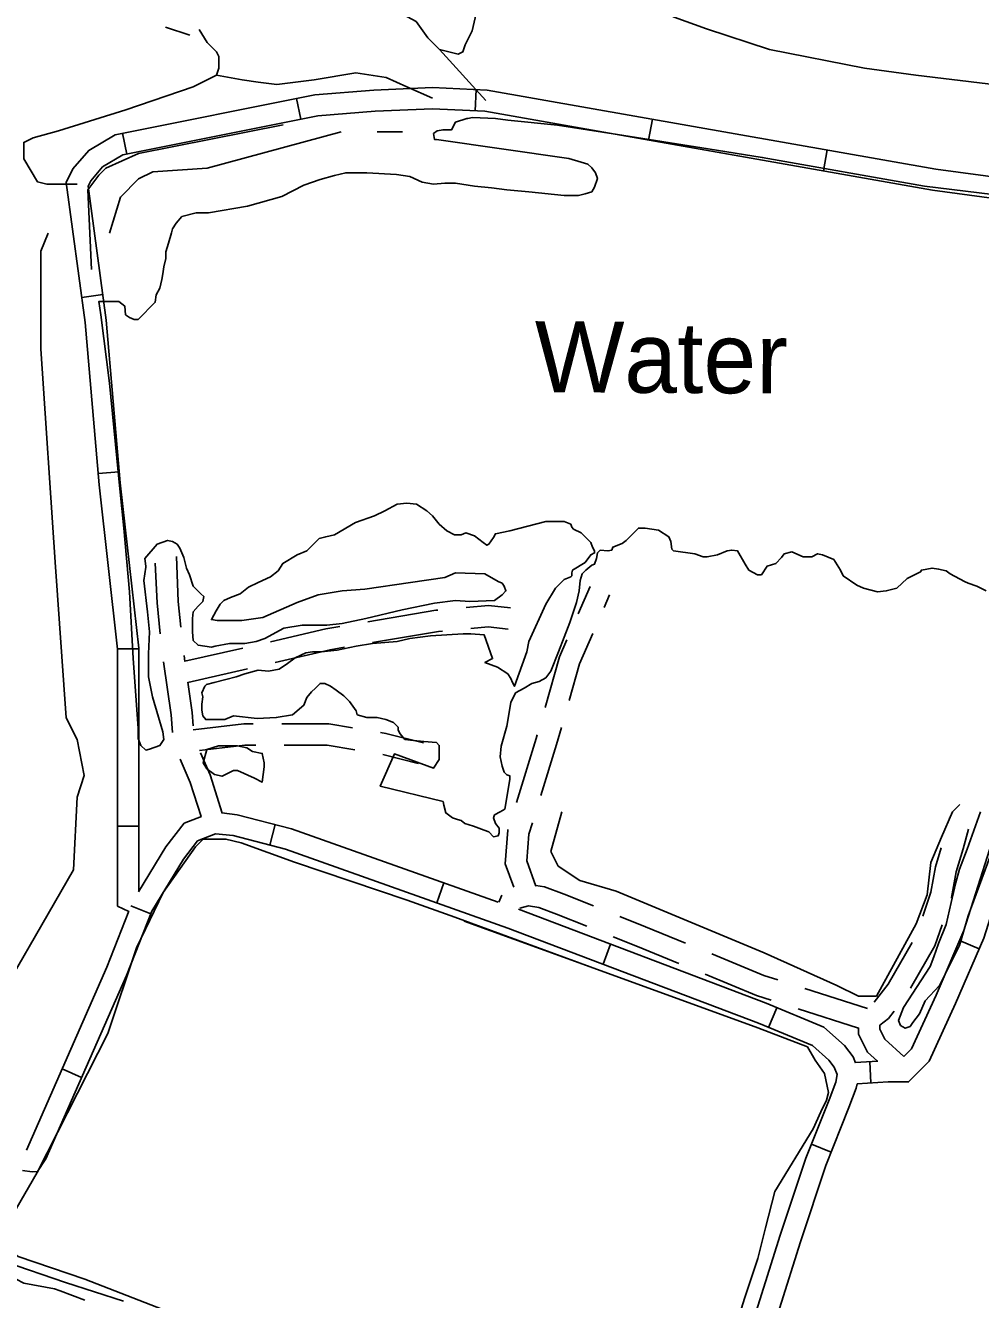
# Model space of a CAD drawing. Extents: x 3355677 to 3393573, y 612928 to 638357.
# Drawn here: x 3373580 to 3374925, y 633662 to 635458 of the extents above; entities that cross this region are included whole.
import ezdxf

# ---------------------------------------------------------------- set-up
doc = ezdxf.new("R2010")
doc.units = 0
for name, color, linetype in [('V-RIVR-IDEN', 7, 'Continuous'), ('V-ROAD-CNTR', 7, 'Continuous'), ('V-TOPO-SHOR', 7, 'Continuous')]:
    doc.layers.add(name, color=color, linetype=linetype)

msp = doc.modelspace()

# ---------------------------------------------------------------- linework, layer by layer
at = {"layer": 'V-ROAD-CNTR'}
for p, q in [((3373777.1, 635455.1), (3373811.6, 635444.1)), ((3373961.8, 635354.8), (3373967.7, 635325.4)), ((3374214.5, 635367.2), (3374213.2, 635337.3)), ((3374462.9, 635325.6), (3374457.7, 635296)), ((3373716.7, 635305.8), (3373722.5, 635276.4)), ((3374709.1, 635282.2), (3374703.9, 635252.6)), ((3373659.1, 635074.4), (3373688.8, 635078.5)), ((3373682.1, 634826.3), (3373712, 634828.8)), ((3374358.2, 634628.4), (3374375.1, 634667.2)), ((3374394.8, 634637.4), (3374402.6, 634655.3)), ((3373709.6, 634579.1), (3373739.6, 634579.1)), ((3373804.5, 634561.7), (3373886.2, 634580.1)), ((3373808.7, 634531.9), (3373892.8, 634550.8)), ((3374083.2, 634430.1), (3374133.2, 634417.6)), ((3373931.8, 634331.5), (3373924.2, 634302.4)), ((3374880.5, 634337.5), (3374881.5, 634341.2)), ((3373709.6, 634329.1), (3373739.6, 634329.1)), ((3374169.3, 634249.5), (3374159.2, 634221.2)), ((3374250.8, 634232.1), (3374246.7, 634222.3)), ((3373728.4, 634217), (3373756.4, 634206)), ((3374404.1, 634162.9), (3374393.5, 634134.9)), ((3374923.1, 634156.3), (3374895.5, 634168.2)), ((3374765.8, 634072.5), (3374677.7, 634100.6)), ((3374638.1, 634073.5), (3374626.6, 634045.8)), ((3374753.4, 634044.9), (3374668.5, 634072)), ((3374770.8, 633967.5), (3374769.1, 633997.4)), ((3373631.6, 633987.2), (3373659, 633975.2)), ((3374714.8, 633870.1), (3374687, 633881.3))]:
    msp.add_line(p, q, dxfattribs=at)
for points in [[(3373774.9, 635622.4), (3373950.4, 635547.9), (3374009.3, 635521.8), (3374094.3, 635482.5), (3374130.3, 635462.9), (3374146.7, 635440), (3374163.1, 635423.6), (3374228.5, 635351.6)], [(3374163.1, 635423.6), (3374189.2, 635417.1), (3374195.8, 635420.3), (3374199, 635430.1), (3374208.9, 635449.8), (3374221.9, 635505.4), (3374228.5, 635528.3), (3374221.9, 635551.2), (3374218.7, 635574.1), (3374212.1, 635590.5), (3374205.6, 635603.6), (3374205.6, 635617.6)], [(3374230.8, 635613.8), (3374251.4, 635603.6), (3374339.7, 635554.5), (3374418.3, 635508.7), (3374493.5, 635469.4), (3374539.3, 635453), (3374627.7, 635423.6), (3374761.8, 635397.4), (3374833.8, 635387.6), (3375075.9, 635358.2), (3375341, 635335.3), (3375422.8, 635318.9), (3375471.9, 635305.8), (3375478.4, 635299.3), (3375484.9, 635286.2), (3375481.7, 635263.3), (3375449, 635165.1), (3375344.2, 634900.1), (3375265.7, 634697.2), (3375213.4, 634556.5), (3375118.5, 634275.1), (3375102.1, 634242.4), (3375092.3, 634229.3), (3375082.7, 634224.5)], [(3373652.6, 635233.8), (3373610.1, 635233.8), (3373597, 635237.1), (3373577.4, 635269.8), (3373577.4, 635292.7), (3373590.5, 635299.3), (3373626.4, 635309.1), (3373721.3, 635338.5), (3373816.2, 635371.2), (3373848.9, 635387.6), (3373852.2, 635397.4), (3373852.2, 635413.8), (3373848.9, 635420.3), (3373835.9, 635433.4), (3373824.4, 635452)], [(3374153.2, 635354.9), (3374117.2, 635371.2), (3374087.8, 635384.3), (3374045.3, 635390.9), (3373986.4, 635381.1), (3373934, 635374.5), (3373907.8, 635377.8), (3373884.9, 635381.1), (3373848.9, 635387.6)], [(3373725.3, 634208.9), (3373709.6, 634216.8), (3373709.6, 634432.2), (3373709.6, 634578.6), (3373683.5, 634810.3), (3373663.9, 635039.1), (3373637.1, 635236.4), (3373646.6, 635255.3), (3373669, 635281.4), (3373706, 635303.6), (3373987.6, 635360), (3374070.5, 635366.6), (3374153.3, 635369.9), (3374230.1, 635366.6), (3374862.3, 635255.2), (3375103.7, 635222.6), (3375189.6, 635216), (3375207, 635211.6), (3375243.8, 635183), (3375248.1, 635148.8), (3375241.2, 635089.8), (3375165.4, 634869.1), (3375002, 634382), (3374992.3, 634346.4)], [(3373739.6, 634237.5), (3373739.6, 634432.2), (3373739.6, 634580.3), (3373713.4, 634813.2), (3373693.7, 635042.4), (3373668.1, 635231.3), (3373671.8, 635238.5), (3373688.6, 635258.2), (3373717, 635275.2), (3373991.7, 635330.2), (3374072.3, 635336.6), (3374153.2, 635339.9), (3374226.9, 635336.7), (3374857.7, 635225.5), (3375100.5, 635192.7), (3375184.8, 635186.2), (3375193.6, 635184), (3375215.6, 635166.9), (3375217.9, 635148.7), (3375211.7, 635096.5), (3375137, 634878.7), (3374973.2, 634390.7), (3374963.3, 634354.3)], [(3373798.8, 634609.6), (3373795.2, 634645.9), (3373792.4, 634709.4)], [(3373769.6, 634600.4), (3373765.3, 634643.8), (3373762.8, 634700.1)], [(3374200.7, 634637.5), (3374231.9, 634640.3), (3374262.9, 634636.9)], [(3374062.2, 634617.3), (3374157.8, 634633.6), (3374160.8, 634633.8)], [(3373925.2, 634589), (3374003, 634607.2), (3374022.8, 634610.6)], [(3374068.8, 634588), (3374161.7, 634603.8), (3374167.4, 634604.3)], [(3374207.3, 634607.9), (3374231.6, 634610.2), (3374259.6, 634607)], [(3374345.7, 634506.5), (3374360.4, 634558), (3374378.9, 634600.7)], [(3374311.7, 634496.7), (3374332.1, 634568.1), (3374342.3, 634591.7)], [(3373804.5, 634561.3), (3373803.3, 634569.9)], [(3373931.7, 634559.8), (3374009, 634577.8), (3374029.4, 634581.3)], [(3373787, 634461.5), (3373784.9, 634486.1), (3373774.3, 634560.7)], [(3373816.3, 634470.8), (3373814.8, 634489.5), (3373808.7, 634532.1)], [(3373816.3, 634465.2), (3373887.3, 634473.4), (3373900.8, 634473.4)], [(3373940.8, 634473.4), (3374007.2, 634473.4), (3374040.4, 634467.8)], [(3374079.8, 634461.3), (3374087.6, 634460), (3374140.5, 634446.7)], [(3374271.4, 634362.6), (3374299.2, 634452.8), (3374300.7, 634458.2)], [(3374305.8, 634372.4), (3374327.9, 634444.3), (3374334.8, 634468.1)], [(3373825, 634436), (3373889.1, 634443.4), (3373904.3, 634443.4)], [(3373944.3, 634443.4), (3374004.8, 634443.4), (3374043.8, 634436.9)], [(3373827.2, 634342.8), (3373812, 634390.9), (3373797.7, 634423.5)], [(3373857, 634347.8), (3373840.1, 634401.5), (3373826.5, 634432.6)], [(3375076.1, 634237.8), (3375070, 634248.6), (3375040.9, 634329.5), (3375024.9, 634369.6), (3374999.4, 634376), (3374967.2, 634362.1), (3374947.6, 634326.9), (3374901.5, 634182.2), (3374862.6, 634091.4), (3374827.8, 634015.5), (3374816.9, 634004.6)], [(3373739.1, 634236.6), (3373777.7, 634300), (3373803.6, 634333.3), (3373827.7, 634343)], [(3373856.7, 634347.9), (3373877.9, 634345.5), (3373954.8, 634325.5), (3374245.9, 634222.4)], [(3374299, 634244.8), (3374286.2, 634280.4), (3374289.1, 634318.1), (3374294.1, 634334.1)], [(3375049.8, 634223.2), (3375042.6, 634236.2), (3375012.8, 634318.9), (3375002.7, 634344.2), (3375002, 634344.4), (3374988.4, 634338.6), (3374975.3, 634315), (3374929.7, 634171.7), (3374890.1, 634079.3), (3374852.9, 633998.1), (3374823.7, 633968.9), (3374795, 633968.9), (3374751.4, 633966.3)], [(3373608.8, 633860.7), (3373722.1, 634118.9), (3373757.7, 634209.5), (3373802.4, 634283), (3373822.3, 634308.5), (3373847.7, 634318.7), (3373872.4, 634316), (3373946, 634296.8), (3374259.3, 634185.8), (3374612.3, 634051.8), (3374688.4, 634020.1), (3374711.5, 633999.8), (3374719.2, 633989.6), (3374723.3, 633979.2), (3374721.2, 633968.4), (3374711.9, 633943.5), (3374679, 633861.5), (3374642.9, 633752.9), (3374554.6, 633471.9)], [(3374267.7, 634243.2), (3374255.8, 634276.4), (3374259.5, 634323.7), (3374259.7, 634324.4)], [(3374884.1, 634227.9), (3374884.4, 634228.9), (3374891, 634265.1), (3374900.6, 634297.2), (3374908.1, 634324.9)], [(3374843.8, 634202.6), (3374845.8, 634208.1), (3374855.2, 634236.3), (3374861.7, 634272.1), (3374869.8, 634298.9)], [(3374379.8, 634217), (3374338.6, 634233.5), (3374310.9, 634243.9), (3374298.9, 634245.9)], [(3373581.3, 633872.8), (3373694.4, 634130.4), (3373725.4, 634209.3)], [(3374274.3, 634212.2), (3374623.4, 634079.7), (3374704.4, 634045.9), (3374733.6, 634020.3), (3374745.6, 634004.4), (3374749, 633995.9)], [(3374370.6, 634188.4), (3374327.8, 634205.5), (3374303.1, 634214.8), (3374288.3, 634217.2), (3374276.3, 634213.8)], [(3374509.5, 634164.5), (3374453.4, 634187.6), (3374416.9, 634202.2)], [(3374826.4, 634101), (3374860.6, 634160.8), (3374871.2, 634190.1)], [(3374500.4, 634135.8), (3374442.1, 634159.8), (3374407.8, 634173.5)], [(3374775.3, 634081.3), (3374795.1, 634106.8), (3374828.8, 634165.6)], [(3374639.6, 634112.8), (3374619.7, 634119.1), (3374546.5, 634149.2)], [(3374630.4, 634084.2), (3374609.4, 634090.9), (3374537.4, 634120.6)], [(3374817, 634004.7), (3374790.4, 634029.1), (3374783.4, 634043.1), (3374783.4, 634048.7), (3374795.5, 634058.4), (3374803.3, 634068.4)], [(3374779.8, 633998.1), (3374766, 634010.7), (3374753.4, 634036), (3374753.4, 634045.1)], [(3374780.5, 633998.1), (3374748.8, 633996.3)], [(3374751.4, 633966.4), (3374750.1, 633960.2), (3374739.8, 633932.7), (3374707.2, 633851.1), (3374671.4, 633743.7), (3374582.9, 633462), (3374428.6, 633064.6), (3374389, 632995.2), (3374372.5, 632962.4), (3374362.7, 632946), (3374354, 632928.5), (3374325.9, 632916.5), (3374155.4, 632847.6), (3374155, 632847.5)], [(3373575.6, 633844), (3373589.4, 633842.1), (3373596.7, 633842.7), (3373608.8, 633860.7)], [(3373335.2, 633656.7), (3373417, 633692.7), (3373453, 633705.8), (3373508.7, 633718.9), (3373551.2, 633715.6), (3373636.3, 633686.2), (3373718.1, 633660)]]:
    msp.add_lwpolyline(points, dxfattribs=at)
at = {"layer": 'V-TOPO-SHOR'}
msp.add_line((3374075.4, 635307.6), (3374111.1, 635307.6), dxfattribs=at)
for points in [[(3374933.3, 634660.7), (3374919.8, 634667.4), (3374907.8, 634671.5), (3374902.4, 634674.1), (3374882.3, 634684.9), (3374876.9, 634688.9), (3374866.1, 634691.6), (3374856.8, 634692.9), (3374842, 634690.2), (3374840.6, 634687.6), (3374821.8, 634678.2), (3374807.1, 634664.7), (3374792.3, 634660.7), (3374780.2, 634659.4), (3374760.1, 634664.7), (3374750.7, 634668.8), (3374731.9, 634682.2), (3374727.9, 634690.2), (3374718.5, 634705), (3374702.4, 634711.7), (3374695.7, 634713.1), (3374687.6, 634709), (3374675.5, 634709), (3374659.4, 634715.8), (3374648.7, 634713.1), (3374644.6, 634707.7), (3374636.6, 634699.6), (3374624.5, 634695.6), (3374616.4, 634683.5), (3374611.1, 634683.5), (3374599, 634690.2), (3374593.6, 634698.3), (3374582.9, 634717.1), (3374574.8, 634718.4), (3374568.1, 634717.1), (3374554.7, 634711.7), (3374539.9, 634709), (3374534.6, 634709), (3374522.5, 634713.1), (3374492.9, 634717.1), (3374490.3, 634719.8), (3374488.9, 634730.5), (3374486.2, 634737.2), (3374471.5, 634746.6), (3374452.7, 634749.3), (3374443.3, 634749.3), (3374435.2, 634741.3), (3374425.8, 634731.9), (3374420.4, 634727.8), (3374407, 634722.5), (3374405.7, 634718.4), (3374400.3, 634717.1), (3374389.6, 634718.4), (3374385.5, 634714.4), (3374384.2, 634706.4), (3374381.5, 634698.3), (3374377.5, 634697), (3374369.4, 634690.2), (3374364.1, 634684.9), (3374361.4, 634675.5), (3374360, 634660.7), (3374356, 634644.6), (3374346.6, 634616.4), (3374330.5, 634574.8), (3374319.8, 634547.9), (3374313, 634538.5), (3374303.6, 634533.2), (3374292.9, 634530.5), (3374282.2, 634523.8), (3374270.1, 634517.1), (3374263.4, 634503.6), (3374258, 634470.1), (3374250, 634441.9), (3374248.6, 634427.1), (3374251.3, 634413.7), (3374254, 634405.6), (3374258, 634401.6), (3374262, 634400.3), (3374262, 634394.9), (3374255.3, 634353.3), (3374248.6, 634349.3), (3374240.6, 634345.2), (3374239.2, 634341.2), (3374241.9, 634333.1), (3374247.3, 634326.4), (3374247.3, 634319.7), (3374245.9, 634315.7), (3374239.2, 634314.4), (3374232.5, 634321.1), (3374225.8, 634323.7), (3374211, 634329.1), (3374198.9, 634333.1), (3374193.6, 634337.2), (3374188.2, 634338.5), (3374181.5, 634341.2), (3374172.1, 634347.9), (3374169.4, 634358.7), (3374168.1, 634364), (3374079.5, 634385.5), (3374099.6, 634431.1), (3374154.6, 634411), (3374162.7, 634423.1), (3374162.7, 634432.5), (3374162.7, 634443.2), (3374158.7, 634447.3), (3374141.2, 634448.6), (3374126.4, 634449.9), (3374114.4, 634451.3), (3374107.6, 634459.3), (3374105, 634464.7), (3374105, 634468.7), (3374098.2, 634475.4), (3374087.5, 634479.5), (3374075.4, 634482.2), (3374063.3, 634482.2), (3374060.7, 634482.2), (3374047.2, 634486.2), (3374045.9, 634491.6), (3374036.5, 634505), (3374028.4, 634513), (3374017.7, 634521.1), (3374009.6, 634526.5), (3374001.6, 634530.5), (3373994.9, 634530.5), (3373988.2, 634523.8), (3373982.8, 634518.4), (3373976.1, 634510.4), (3373972.1, 634499.6), (3373955.9, 634486.2), (3373933.1, 634482.2), (3373906.3, 634480.8), (3373872.7, 634484.8), (3373860.6, 634479.5), (3373833.8, 634479.5), (3373829.8, 634484.8), (3373828.4, 634492.9), (3373828.4, 634501), (3373829.8, 634511.7), (3373828.4, 634517.1), (3373832.4, 634526.5), (3373835.1, 634529.1), (3373845.9, 634531.8), (3373862, 634535.9), (3373876.7, 634539.9), (3373888.8, 634543.9), (3373907.6, 634549.3), (3373922.4, 634547.9), (3373937.2, 634550.6), (3373949.2, 634558.7), (3373960, 634566.7), (3373974.7, 634573.5), (3373984.1, 634574.8), (3373996.2, 634574.8), (3374019, 634577.5), (3374045.9, 634582.8), (3374068.7, 634586.9), (3374103.6, 634589.6), (3374121.1, 634593.6), (3374150.6, 634597.6), (3374196.3, 634600.3), (3374207, 634600.3), (3374225.8, 634599), (3374237.9, 634565.4), (3374227.1, 634560), (3374244.6, 634553.3), (3374259.3, 634543.9), (3374263.4, 634537.2), (3374266.1, 634531.8), (3374268.7, 634526.5), (3374286.2, 634574.8), (3374288.9, 634589.6), (3374313, 634641.9), (3374326.5, 634664.7), (3374338.6, 634676.8), (3374348, 634680.8), (3374349.3, 634682.2), (3374349.3, 634686.2), (3374350.6, 634690.2), (3374368.1, 634701), (3374376.1, 634711.7), (3374381.5, 634714.4), (3374381.5, 634717.1), (3374378.8, 634722.5), (3374376.1, 634729.2), (3374362.7, 634742.6), (3374352, 634748), (3374349.3, 634750.7), (3374348, 634754.7), (3374338.6, 634758.7), (3374313, 634758.7), (3374287.5, 634752), (3374262, 634745.3), (3374241.9, 634741.3), (3374239.2, 634735.9), (3374232.5, 634726.5), (3374229.8, 634725.2), (3374224.4, 634729.2), (3374212.4, 634738.6), (3374200.3, 634742.6), (3374193.6, 634739.9), (3374184.2, 634739.9), (3374173.4, 634745.3), (3374162.7, 634754.7), (3374153.3, 634766.8), (3374145.2, 634773.5), (3374130.5, 634782.9), (3374117, 634784.2), (3374103.6, 634782.9), (3374086.2, 634773.5), (3374071.4, 634766.8), (3374044.6, 634757.4), (3374015, 634739.9), (3374002.9, 634737.2), (3373993.5, 634734.5), (3373976.1, 634717.1), (3373962.7, 634711.7), (3373942.5, 634699.6), (3373935.8, 634688.9), (3373925.1, 634680.8), (3373907.6, 634672.8), (3373894.2, 634666.1), (3373882.1, 634656.7), (3373868.7, 634651.3), (3373859.3, 634647.3), (3373853.9, 634641.9), (3373848.5, 634632.5), (3373841.8, 634620.4), (3373849.9, 634619.1), (3373884.8, 634619.1), (3373914.3, 634623.1), (3373962.7, 634644.6), (3373992.2, 634655.3), (3374025.8, 634660.7), (3374058, 634663.4), (3374122.4, 634672.8), (3374170.7, 634679.5), (3374185.5, 634686.2), (3374227.1, 634684.9), (3374245.9, 634674.1), (3374251.3, 634671.5), (3374254, 634667.4), (3374256.7, 634660.7), (3374251.3, 634655.3), (3374240.6, 634647.3), (3374205.6, 634645.9), (3374185.5, 634647.3), (3374156, 634643.3), (3374110.3, 634633.9), (3374059.3, 634621.8), (3374025.8, 634615.1), (3374004.3, 634612.4), (3373969.4, 634612.4), (3373943.9, 634608.4), (3373917, 634593.6), (3373904.9, 634589.6), (3373888.8, 634586.9), (3373867.3, 634586.9), (3373847.2, 634582.8), (3373841.8, 634581.5), (3373823, 634584.2), (3373816.3, 634590.9), (3373815, 634603), (3373815, 634612.4), (3373815, 634621.8), (3373816.3, 634631.2), (3373823, 634639.2), (3373829.8, 634645.9), (3373831.1, 634652.7), (3373827.1, 634656.7), (3373816.3, 634667.4), (3373811, 634683.5), (3373806.9, 634692.9), (3373802.9, 634707.7), (3373797.5, 634721.1), (3373793.5, 634726.5), (3373786.8, 634730.5), (3373780.1, 634731.9), (3373765.3, 634726.5), (3373747.9, 634706.4), (3373749.2, 634695.6), (3373749.2, 634694.3), (3373746.5, 634675.5), (3373751.9, 634631.2), (3373754.6, 634603), (3373753.2, 634572.1), (3373753.2, 634539.9), (3373758.6, 634511.7), (3373773.4, 634462), (3373774.7, 634451.3), (3373769.3, 634443.2), (3373754.6, 634437.9), (3373749.2, 634436.5), (3373742.5, 634443.2), (3373738.5, 634452.6), (3373738.5, 634467.4), (3373731.8, 634565.4), (3373726.4, 634659.4), (3373718.3, 634749.3), (3373713, 634804.4), (3373698.2, 634953.4), (3373686.1, 635050), (3373683.4, 635068.8), (3373711.6, 635068.8), (3373719.7, 635062.1), (3373721, 635050), (3373726.4, 635046), (3373733.1, 635043.3), (3373738.5, 635043.3), (3373762.6, 635067.5), (3373764, 635078.2), (3373769.3, 635087.6), (3373772, 635099.7), (3373773.4, 635107.8), (3373774.7, 635117.2), (3373777.4, 635129.2), (3373777.4, 635138.6), (3373781.4, 635150.7), (3373785.5, 635165.5), (3373786.8, 635170.9), (3373792.2, 635178.9), (3373800.2, 635188.3), (3373820.4, 635193.7), (3373832.4, 635193.7), (3373837.8, 635193.7), (3373892.8, 635203.1), (3373941.2, 635216.5), (3373972.1, 635232.6), (3373994.9, 635240.7), (3374015, 635246), (3374031.1, 635250.1), (3374060.7, 635250.1), (3374102.3, 635247.4), (3374121.1, 635244.7), (3374138.5, 635236.6), (3374154.6, 635234), (3374170.7, 635235.3), (3374185.5, 635235.3), (3374212.4, 635231.3), (3374236.5, 635228.6), (3374258, 635225.9), (3374288.9, 635223.2), (3374338.6, 635217.8), (3374358.7, 635217.8), (3374368.1, 635220.5), (3374377.5, 635223.2), (3374381.5, 635229.9), (3374385.5, 635242), (3374382.9, 635250.1), (3374377.5, 635256.8), (3374372.1, 635262.1), (3374362.7, 635264.8), (3374345.3, 635270.2), (3374158.7, 635297), (3374156, 635297), (3374154.6, 635305.1), (3374160, 635309.1), (3374168.1, 635310.5), (3374178.8, 635310.5), (3374180.1, 635310.5), (3374185.5, 635321.2), (3374201.6, 635326.6), (3374203, 635326.6), (3374209.7, 635327.9), (3374241.9, 635326.6), (3374259.3, 635323.9), (3374329.2, 635317.2), (3374413.7, 635303.8), (3374541.3, 635283.6), (3374617.8, 635271.5), (3374846, 635231.3), (3375000.4, 635212.5)], [(3373672.9, 635113.9), (3373667.8, 635226), (3373683, 635246.4), (3373693.2, 635256.6), (3373739.1, 635277), (3373942.9, 635317.7)], [(3373698.3, 635164.9), (3373713.6, 635215.8), (3373739.1, 635241.3), (3373759.5, 635251.5), (3373835.9, 635256.6), (3374024.5, 635307.6)], [(3373407.9, 634043.8), (3373413, 634028.6), (3373463.9, 634018.4), (3373489.4, 634018.4), (3373514.9, 634038.7), (3373647.4, 634268), (3373652.5, 634370), (3373662.7, 634400.5), (3373652.5, 634451.5), (3373637.2, 634482.1), (3373621.9, 634701.2), (3373601.5, 635001.8), (3373601.5, 635139.4), (3373611.7, 635164.9)], [(3374335.3, 634349.6), (3374320, 634293.5), (3374330.2, 634273.1), (3374360.8, 634252.8), (3374411.7, 634237.5), (3374620.6, 634150.8), (3374722.6, 634105), (3374753.1, 634089.7), (3374778.6, 634089.7), (3374834.7, 634191.6), (3374849.9, 634232.4), (3374855, 634278.2), (3374870.3, 634313.9), (3374885.6, 634349.6), (3374895.8, 634359.8)], [(3374950.7, 634319.7), (3374907.8, 634202.9), (3374895.7, 634161.3), (3374867.5, 634104.9), (3374847.4, 634083.4), (3374839.3, 634064.7), (3374829.9, 634052.6), (3374825.9, 634047.2), (3374819.2, 634044.5), (3374812.5, 634048.5), (3374809.8, 634055.3), (3374816.5, 634074), (3374854.1, 634131.8), (3374859.4, 634145.2), (3374866.1, 634164), (3374876.9, 634190.8), (3374883.6, 634221.7), (3374890.3, 634249.9), (3374895.7, 634268.7), (3374906.4, 634296.9), (3374925.2, 634349.3)], [(3373781.8, 633645.1), (3373663.6, 633690.8), (3373569.6, 633723), (3373558.9, 633731), (3373553.5, 633741.8), (3373553.5, 633749.8), (3373556.2, 633771.3), (3373567, 633790.1), (3373596.5, 633841.1), (3373695.8, 634037.1), (3373736.1, 634158), (3373773.7, 634235.8), (3373819.3, 634300.3), (3373830.1, 634311), (3373846.2, 634311), (3373862.3, 634311), (3373883.8, 634305.6), (3373959, 634278.8), (3374117.4, 634225.1), (3374184.5, 634200.9), (3374375.1, 634131.1)], [(3374197.9, 634195.5), (3374375.1, 634131.1), (3374611.4, 634045.2), (3374681.2, 634018.3), (3374692, 633999.5), (3374705.4, 633980.7), (3374710.8, 633953.9), (3374708.1, 633943.2), (3374700, 633927), (3374689.3, 633902.9), (3374635.6, 633814.3), (3374622.2, 633763.3), (3374611.4, 633720.3), (3374592.6, 633663.9), (3374555, 633543.1)], [(3373397.8, 633661.2), (3373454.2, 633693.5), (3373467.6, 633701.5), (3373481, 633704.2), (3373499.8, 633701.5), (3373515.9, 633693.5), (3373532.1, 633688.1), (3373567, 633690.8), (3373577.7, 633685.4), (3373620.7, 633677.3), (3373628.7, 633674.7), (3373663.6, 633661.2)]]:
    msp.add_lwpolyline(points, dxfattribs=at)
msp.add_lwpolyline([(3373878.4, 634442.6), (3373851.6, 634442.6), (3373835.5, 634437.2), (3373830.1, 634418.4), (3373835.5, 634410.3), (3373846.2, 634402.3), (3373856.9, 634399.6), (3373873, 634407.7), (3373878.4, 634407.7), (3373902.6, 634396.9), (3373913.3, 634391.5), (3373916, 634413), (3373916, 634418.4), (3373913.3, 634431.8), (3373899.9, 634434.5), (3373891.8, 634439.9)], close=True, dxfattribs=at)

# ---------------------------------------------------------------- texts
at = {"layer": 'V-RIVR-IDEN'}
msp.add_text('Water', height=100, rotation=359.6707, dxfattribs=at).set_placement((3374296.9, 634940.9))

doc.saveas('drawing.dxf')
